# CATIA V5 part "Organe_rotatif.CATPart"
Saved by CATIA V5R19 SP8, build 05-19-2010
Part number: Organe_rotatif
Bounding box of the stored display mesh (mm): x 0 to 18, y -110 to 110, z -109.814 to 109.814
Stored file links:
  G:\EU_thinkMotion\CFAO_2010\SIL_groupe2\SIL_groupe2\msauret\Brevet_Sauret_parametre\Organe_rotatif.CATPart
  F:\Brevet_Sauret paramétré\Product3.CATProduct
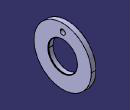
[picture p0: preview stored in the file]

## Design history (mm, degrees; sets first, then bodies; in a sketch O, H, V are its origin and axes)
Set1
  Plane1 to Plane3: linked copy from another document
  Point1: linked copy from another document
Body1 (main body)
  Sketch1 on Plane1, origin (0, 0, 0), H (0, 1, 0), V (0, 0, 1)
    circle A1 centre (0, 0) radius 110
    point P1 (0, 0)
    coincidence: P1 V
  Pad1: profile Sketch1, direction (1, 0, 0), up to Plane2
  Sketch2 on Plane1, origin (0, 0, 0), H (0, 1, 0), V (0, 0, 1)
    circle A1 centre (0, 0) radius 55
  Pocket1: profile Sketch2, direction (-1, 0, 0), up to Plane2
  Sketch3 on Plane2, origin (18, 0, 0), H (0, 1, 0), V (0, 0, 1)
    circle A1 centre (0, 0) radius 57
  Pocket2: profile Sketch3, direction (-1, 0, 0), length 2
  Sketch4 on Plane2, origin (18, 0, 0), H (0, 1, 0), V (0, 0, 1)
    circle A1 centre (0, 80) radius 10
    point P1 (0, 80)
    reference projected point E1 (0, 80) from Point1
    distance P1 E1 = 0
    coincidence: P1 V
  Pocket3: profile Sketch4, direction (-1, 0, 0), up to Plane1
  Sketch5 on yz-plane, origin (0, 0, 0), H (0, 1, 0), V (0, 0, 1)
    circle A1 centre (0, 0) radius 55
    reference projected circle E1 centre (0, 0) radius 55 from edge [face of Pocket1 from Sketch2.A1 | start face of Pad1]
    coincidence: E1 A1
